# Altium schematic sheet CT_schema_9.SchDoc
size 278 x 170 mm
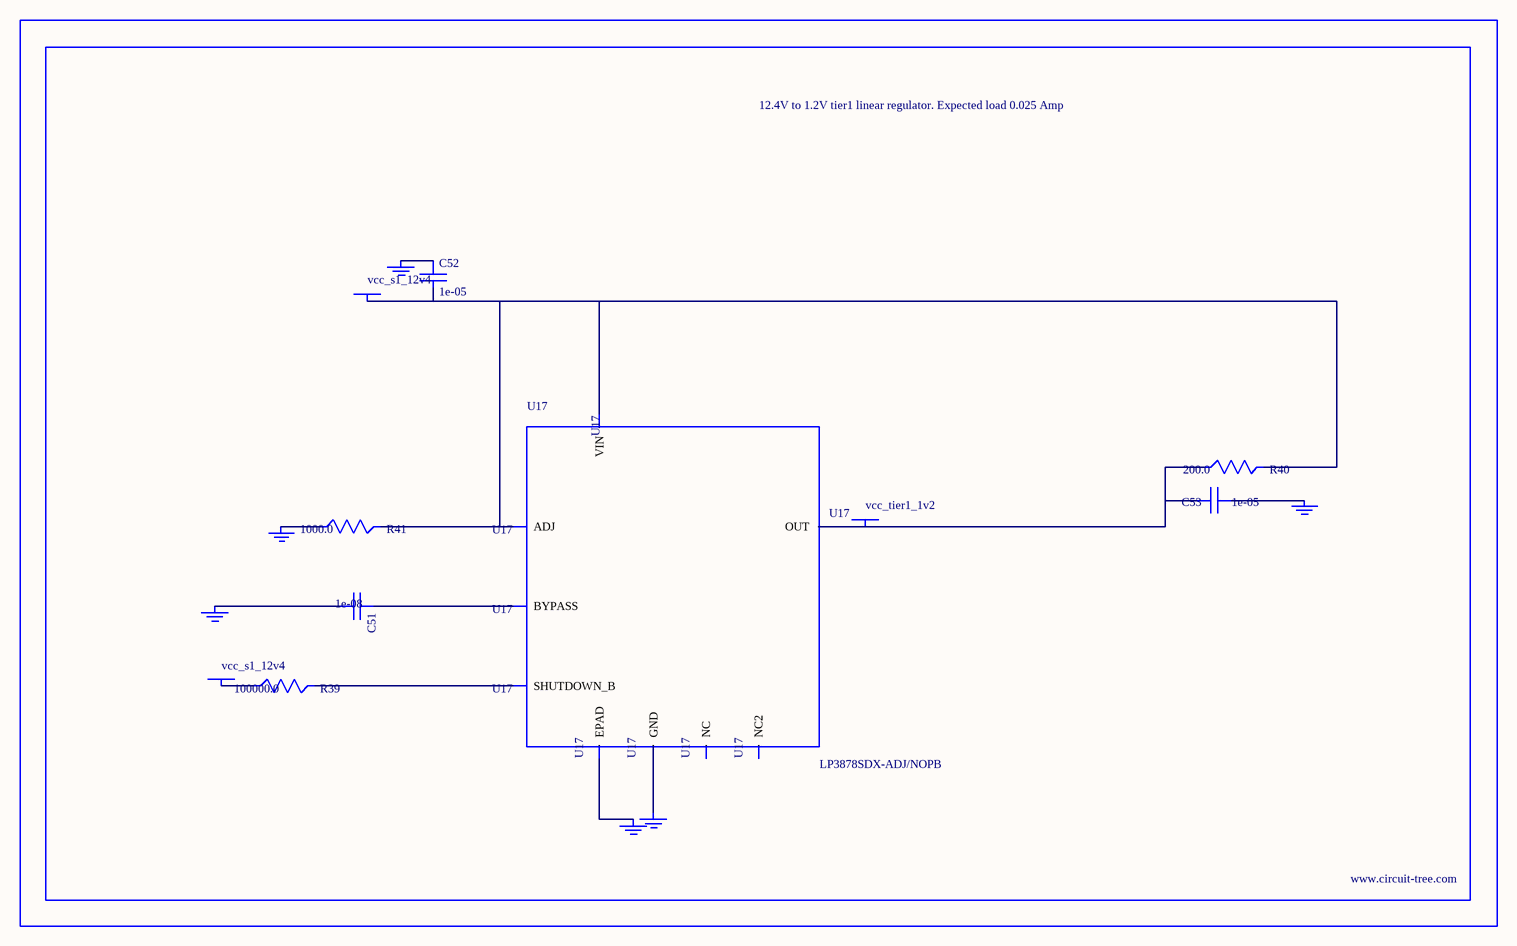
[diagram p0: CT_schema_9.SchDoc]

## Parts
BORDER8  (no value)
C51  1e-08  [C0402]
C52  1e-05  [C1210]
C53  1e-05  [C0805]
GND_INSTANCE_8_0  (no value)
GND_INSTANCE_8_1  (no value)
GND_INSTANCE_8_2  (no value)
GND_INSTANCE_8_3  (no value)
GND_INSTANCE_8_4  (no value)
GND_INSTANCE_8_5  (no value)
POWER_INSTANCE_8_0  vcc_s1_12v4
POWER_INSTANCE_8_1  vcc_s1_12v4
POWER_INSTANCE_8_2  vcc_tier1_1v2
R39  100000.0  [R0603]
R40  200.0  [R0603]
R41  1000.0  [R0603]
U17  LP3878SDX-ADJ/NOPB  [WSON-8]

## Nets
NetC51_1: C51.1 U17.1(BYPASS)
NetC51_2: C51.2 GND_INSTANCE_8_0.0(GND)
NetC52_1: C52.1 GND_INSTANCE_8_1.0(GND)
NetC52_2: C52.2 POWER_INSTANCE_8_0.0(PWR) R40.2 R41.2 U17.4(VIN) U17.6(ADJ)
NetC53_1: C53.1 GND_INSTANCE_8_2.0(GND)
NetC53_2: C53.2 POWER_INSTANCE_8_2.0(PWR) R40.1 U17.5(OUT)
NetGND_INSTANCE_8_3_0: GND_INSTANCE_8_3.0(GND) R41.1
NetGND_INSTANCE_8_4_0: GND_INSTANCE_8_4.0(GND) U17.PAD(EPAD)
NetGND_INSTANCE_8_5_0: GND_INSTANCE_8_5.0(GND) U17.3(GND)
NetPOWER_INSTANCE_8_1_0: POWER_INSTANCE_8_1.0(PWR) R39.1
NetR39_2: R39.2 U17.8(SHUTDOWN_B)

Not connected (* = marked no-connect by the designer): U17 2(NC) 7(NC2)

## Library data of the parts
BORDER8 = BORDER_PAGE8
C51 = C0402C103K3RAC
C52 = C1210C106K5PACTU
C53 = GRM219R60J106ME19D
GND_INSTANCE_8_0-GND_INSTANCE_8_5 = GND
POWER_INSTANCE_8_0-POWER_INSTANCE_8_2 = PWR
R39 = RC0603JR-07100KL
R40 = RC0603JR-07200RL
R41 = RC0603JR-071KL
